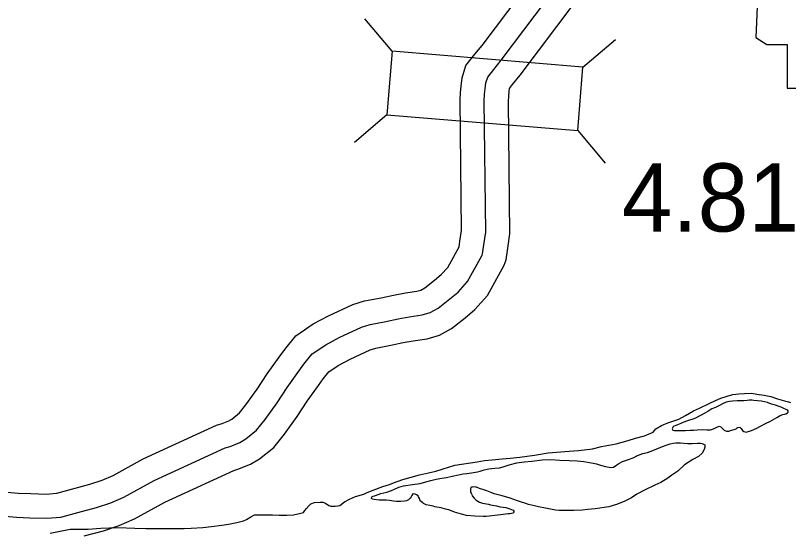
# Model space of a CAD drawing. Extents: x 31699 to 244310, y -8841 to 11474.
# Drawn here: x 98137.1 to 98456.9, y 2842.4 to 3055.8 of the extents above; entities that cross this region are included whole.
import ezdxf

# ---------------------------------------------------------------- set-up
doc = ezdxf.new("R2010")
doc.units = 0
for name, color, linetype in [('B_Logo', 7, 'Continuous'), ('G-ANNO-TEXT', 7, 'Continuous'), ('Level 55', 7, 'Continuous'), ('R_Draft', 7, 'Continuous'), ('R_XS_EARTHWORK_STAGE1', 7, 'Continuous'), ('S_WALL', 7, 'Continuous')]:
    doc.layers.add(name, color=color, linetype=linetype)

msp = doc.modelspace()

# ---------------------------------------------------------------- linework, layer by layer
at = {"layer": 'B_Logo'}
msp.add_lwpolyline([(98132.93, 2848.75), (98137.53, 2848.36), (98143.06, 2848.11), (98150.11, 2847.92), (98155.91, 2848.4), (98162.82, 2850.28), (98170.61, 2852.37), (98176.46, 2854.25), (98181.92, 2856.67), (98194.41, 2863.5), (98223.87, 2877.05), (98225.87, 2877.65), (98229.86, 2879.2), (98232.32, 2880.74), (98236.83, 2884.29), (98240.42, 2888.77), (98245.32, 2895.58), (98249.44, 2901.93), (98254.28, 2908.69), (98256.4, 2911.63), (98259.85, 2915.91), (98265.43, 2919.66), (98271.02, 2922.61), (98280.19, 2926.97), (98283.85, 2928.04), (98290.37, 2929.26), (98295.43, 2930.4), (98300.02, 2931.21), (98305.28, 2931.96), (98308.61, 2932.97), (98312, 2934.78), (98316.78, 2938.59), (98320.17, 2941.4), (98324.15, 2945.82), (98330.11, 2956.71), (98330.31, 2957.24), (98330.83, 2960.98), (98331.62, 2966.19), (98331, 3020.52), (98331.19, 3023.2), (98331.39, 3025.53), (98331.71, 3027.94), (98332.44, 3030.34), (98334.96, 3033.48), (98338.01, 3037.29), (98375.89, 3087.57)], dxfattribs=at)
at = {"layer": 'G-ANNO-TEXT'}
msp.add_lwpolyline([(98440.55, 3131.83), (98445.63, 3097.99), (98443.37, 3046.68), (98447.88, 3043.86), (98456.34, 3043.86), (98456.34, 3025.81), (98527.4, 3025.81), (98530.78, 3033.14), (98529.65, 3044.98), (98531.34, 3058.52), (98537.55, 3069.23), (98541.49, 3077.13), (98547.13, 3085.59), (98550.52, 3094.61), (98553.34, 3101.94), (98558.41, 3108.14), (98559.54, 3112.09), (98557.28, 3114.91), (98539.8, 3114.91), (98543.75, 3122.81), (98544.31, 3127.88), (98541.98, 3131.78)], close=True, dxfattribs=at)
at = {"layer": 'Level 55'}
for points in [[(98133.66, 2858.73), (98138.18, 2858.34), (98143.42, 2858.1), (98149.83, 2857.93), (98154.16, 2858.29), (98160.22, 2859.94), (98167.78, 2861.97), (98172.9, 2863.61), (98177.48, 2865.64), (98189.92, 2872.44), (98220.31, 2886.42), (98222.61, 2887.11), (98225.36, 2888.18), (98226.56, 2888.93), (98229.75, 2891.44), (98232.45, 2894.81), (98237.06, 2901.23), (98241.17, 2907.57), (98246.16, 2914.53), (98248.45, 2917.7), (98253.02, 2923.36), (98260.29, 2928.25), (98266.53, 2931.55), (98276.61, 2936.34), (98281.52, 2937.78), (98288.35, 2939.05), (98293.45, 2940.21), (98298.45, 2941.09), (98303.11, 2941.75), (98304.76, 2942.25), (98306.48, 2943.17), (98310.47, 2946.35), (98313.23, 2948.64), (98315.94, 2951.65), (98320.63, 2960.21), (98320.94, 2962.42), (98321.61, 2966.88), (98321, 3020.83), (98321.22, 3023.97), (98321.44, 3026.62), (98321.91, 3030.07), (98323.43, 3035.09), (98327.16, 3039.74), (98330.12, 3043.43), (98367.92, 3093.61)], [(98165.43, 2840.63), (98173.43, 2842.77), (98180.03, 2844.89), (98186.35, 2847.69), (98198.91, 2854.56), (98227.43, 2867.68), (98229.13, 2868.19), (98234.36, 2870.22), (98238.07, 2872.55), (98243.92, 2877.14), (98248.38, 2882.72), (98253.59, 2889.94), (98257.7, 2896.3), (98262.4, 2902.85), (98264.35, 2905.56), (98266.68, 2908.45), (98270.57, 2911.06), (98275.5, 2913.66), (98283.77, 2917.59), (98286.18, 2918.3), (98292.39, 2919.46), (98297.41, 2920.6), (98301.59, 2921.34), (98307.44, 2922.17), (98312.45, 2923.68), (98317.51, 2926.39), (98323.09, 2930.83), (98327.11, 2934.17), (98332.36, 2939.99), (98339.23, 2952.55), (98340.06, 2954.78), (98340.73, 2959.55), (98341.63, 2965.5), (98341.01, 3020.22), (98341.16, 3022.42), (98341.33, 3024.45), (98341.49, 3025.65), (98342.76, 3027.23), (98345.91, 3031.16), (98383.86, 3081.53)]]:
    msp.add_lwpolyline(points, dxfattribs=at)
at = {"layer": 'R_Draft'}
for points in [[(98379.47, 2877.58), (98385.59, 2878.66), (98390.51, 2880.01), (98393.64, 2881.02), (98397.36, 2882.03), (98400.95, 2883.5), (98401.95, 2884.84), (98404.34, 2886.31), (98407, 2887.39), (98409.86, 2888.39), (98411.59, 2888.93), (98414.32, 2890.34), (98417.57, 2892.28), (98420.03, 2893.49), (98424.02, 2895.43), (98426.68, 2896.64), (98428.88, 2897.51), (98431.47, 2898.45), (98433.87, 2899.12), (98436.33, 2899.33), (98438.66, 2899.47), (98441.59, 2899.61), (98443.79, 2899.21), (98446.85, 2898.82), (98449.52, 2898.22), (98452.38, 2897.23), (98455.18, 2896.43), (98456.85, 2896.04), (98457.78, 2895.84)], [(98379.47, 2877.58), (98385.59, 2878.66), (98390.51, 2880.01), (98393.64, 2881.02), (98397.36, 2882.03), (98400.95, 2883.5), (98401.95, 2884.84), (98404.34, 2886.31), (98407, 2887.39), (98409.86, 2888.39), (98411.59, 2888.93), (98414.32, 2890.34), (98417.57, 2892.28), (98420.03, 2893.49), (98424.02, 2895.43), (98426.68, 2896.64), (98428.88, 2897.51), (98431.47, 2898.45), (98433.87, 2899.12), (98436.33, 2899.33), (98438.66, 2899.47), (98441.59, 2899.61), (98443.79, 2899.21), (98446.85, 2898.82), (98449.52, 2898.22), (98452.38, 2897.23), (98455.18, 2896.43), (98456.85, 2896.04), (98457.78, 2895.84)], [(98452.07, 2889.55), (98453.47, 2890.36), (98454.6, 2890.76), (98455.2, 2890.96), (98455.73, 2891.16), (98456.53, 2891.5), (98456.72, 2891.83), (98456.72, 2892.03), (98456.59, 2892.43), (98456.26, 2892.76), (98454.99, 2893.36), (98453.86, 2893.83), (98452.59, 2894.29), (98451.46, 2894.62), (98449.92, 2895.15), (98448.26, 2895.75), (98446.99, 2896.02), (98445.59, 2896.28), (98442.53, 2896.67), (98441.73, 2896.74), (98440.73, 2896.74), (98439.8, 2896.6), (98438.4, 2896.53), (98437.4, 2896.46), (98435.61, 2896.53), (98433.74, 2896.39), (98432.54, 2896.25), (98431.15, 2895.85), (98429.55, 2895.18), (98428.29, 2894.51), (98426.69, 2893.77), (98425.16, 2893.1), (98423.57, 2892.09), (98421.97, 2891.29), (98420.71, 2890.49), (98419.64, 2889.95)], [(98452.07, 2889.55), (98453.47, 2890.36), (98454.6, 2890.76), (98455.2, 2890.96), (98455.73, 2891.16), (98456.53, 2891.5), (98456.72, 2891.83), (98456.72, 2892.03), (98456.59, 2892.43), (98456.26, 2892.76), (98454.99, 2893.36), (98453.86, 2893.83), (98452.59, 2894.29), (98451.46, 2894.62), (98449.92, 2895.15), (98448.26, 2895.75), (98446.99, 2896.02), (98445.59, 2896.28), (98442.53, 2896.67), (98441.73, 2896.74), (98440.73, 2896.74), (98439.8, 2896.6), (98438.4, 2896.53), (98437.4, 2896.46), (98435.61, 2896.53), (98433.74, 2896.39), (98432.54, 2896.25), (98431.15, 2895.85), (98429.55, 2895.18), (98428.29, 2894.51), (98426.69, 2893.77), (98425.16, 2893.1), (98423.57, 2892.09), (98421.97, 2891.29), (98420.71, 2890.49), (98419.64, 2889.95)], [(98419.64, 2889.95), (98418.45, 2889.35), (98416.92, 2888.81), (98416.32, 2888.61), (98414.72, 2888), (98413.59, 2887.67), (98412.86, 2887.33), (98412.33, 2887.13), (98411.6, 2886.8), (98410.93, 2886.53), (98410, 2886.12), (98409.47, 2885.99), (98409, 2885.52), (98408.87, 2885.19), (98408.81, 2884.85), (98409.07, 2884.39), (98409.74, 2884.25), (98411.74, 2884.26), (98414.27, 2884.2), (98416.26, 2884.34), (98417.53, 2884.4), (98419.13, 2884.48), (98421.39, 2884.55), (98423.06, 2884.48), (98423.99, 2884.42), (98424.65, 2884.42), (98425.92, 2884.96), (98426.65, 2885.29), (98427.31, 2885.63), (98427.71, 2885.76), (98428.18, 2885.96), (98428.91, 2885.76), (98429.71, 2884.9), (98430.25, 2884.37), (98431.18, 2883.9), (98432.24, 2883.97), (98433.31, 2884.37), (98434.44, 2884.64), (98435.24, 2884.91), (98435.7, 2885.31), (98435.97, 2885.51), (98436.77, 2885.65), (98437.37, 2884.98), (98437.9, 2884.25), (98438.44, 2883.78), (98439.37, 2883.45), (98441.57, 2884.19), (98443.76, 2885.2), (98445.02, 2885.87), (98447.62, 2887.21), (98449.21, 2887.88), (98452.07, 2889.55)], [(98419.64, 2889.95), (98418.45, 2889.35), (98416.92, 2888.81), (98416.32, 2888.61), (98414.72, 2888), (98413.59, 2887.67), (98412.86, 2887.33), (98412.33, 2887.13), (98411.6, 2886.8), (98410.93, 2886.53), (98410, 2886.12), (98409.47, 2885.99), (98409, 2885.52), (98408.87, 2885.19), (98408.81, 2884.85), (98409.07, 2884.39), (98409.74, 2884.25), (98411.74, 2884.26), (98414.27, 2884.2), (98416.26, 2884.34), (98417.53, 2884.4), (98419.13, 2884.48), (98421.39, 2884.55), (98423.06, 2884.48), (98423.99, 2884.42), (98424.65, 2884.42), (98425.92, 2884.96), (98426.65, 2885.29), (98427.31, 2885.63), (98427.71, 2885.76), (98428.18, 2885.96), (98428.91, 2885.76), (98429.71, 2884.9), (98430.25, 2884.37), (98431.18, 2883.9), (98432.24, 2883.97), (98433.31, 2884.37), (98434.44, 2884.64), (98435.24, 2884.91), (98435.7, 2885.31), (98435.97, 2885.51), (98436.77, 2885.65), (98437.37, 2884.98), (98437.9, 2884.25), (98438.44, 2883.78), (98439.37, 2883.45), (98441.57, 2884.19), (98443.76, 2885.2), (98445.02, 2885.87), (98447.62, 2887.21), (98449.21, 2887.88), (98452.07, 2889.55)], [(98400.71, 2875.96), (98402.44, 2876.56), (98404.77, 2877.57), (98406.23, 2878.17), (98407.96, 2878.64), (98409.16, 2878.91), (98410.22, 2879.05), (98412.15, 2879.05), (98413.62, 2878.99), (98415.28, 2878.86), (98417.01, 2878.86), (98419.21, 2878.93), (98420.47, 2879), (98421.14, 2878.87), (98421.74, 2878.61), (98422.27, 2878.21), (98422.34, 2877.87), (98422.28, 2877.27), (98421.95, 2876.34), (98421.22, 2874.87), (98419.69, 2873.46), (98417.3, 2872.26), (98413.84, 2870.05), (98411.12, 2867.44), (98408.66, 2865.76), (98406.93, 2864.49), (98404.14, 2862.75), (98401.61, 2861.61), (98397.56, 2859.73), (98394.1, 2857.85), (98391.91, 2856.38), (98388.92, 2854.91), (98385.79, 2853.63), (98382.6, 2852.69), (98376.94, 2851.81), (98373.88, 2851.54), (98371.48, 2851.26), (98368.09, 2851.12), (98363.49, 2851.18), (98362.03, 2851.11), (98360.5, 2851.31), (98356.3, 2852.03), (98353.5, 2852.63), (98351.84, 2853.02), (98349.3, 2853.62), (98348.17, 2854.02), (98346.5, 2854.62), (98344.77, 2855.15), (98341.77, 2856.27), (98338.38, 2857.13), (98336.78, 2857.6), (98335.18, 2858.06), (98334.18, 2858.39), (98332.11, 2859.19), (98330.78, 2859.72), (98329.11, 2860.19), (98327.78, 2860.72), (98327.45, 2860.78), (98326.45, 2860.85), (98326.05, 2860.78), (98325.78, 2860.71), (98325.45, 2860.58), (98325.32, 2859.98), (98325.32, 2859.64), (98325.32, 2859.04), (98325.39, 2858.71), (98325.59, 2858.31), (98325.86, 2857.78), (98326.06, 2857.24), (98326.79, 2856.24), (98327.66, 2855.44), (98329.06, 2854.64), (98330.26, 2854.18), (98332.79, 2853.72), (98333.66, 2853.45), (98336.06, 2852.99), (98337.66, 2852.66), (98338.79, 2852.53), (98339.92, 2852.33), (98340.72, 2852.07), (98341.59, 2851.87), (98342.32, 2851.54), (98342.92, 2851.2), (98343.32, 2850.87), (98343.32, 2850.47), (98343.12, 2850.14), (98342.79, 2850), (98341.72, 2849.8), (98340.86, 2849.73), (98339.86, 2849.66), (98338.86, 2849.53), (98335.4, 2849.12), (98331.87, 2848.71), (98330.54, 2848.64), (98327.08, 2848.83)], [(98400.71, 2875.96), (98402.44, 2876.56), (98404.77, 2877.57), (98406.23, 2878.17), (98407.96, 2878.64), (98409.16, 2878.91), (98410.22, 2879.05), (98412.15, 2879.05), (98413.62, 2878.99), (98415.28, 2878.86), (98417.01, 2878.86), (98419.21, 2878.93), (98420.47, 2879), (98421.14, 2878.87), (98421.74, 2878.61), (98422.27, 2878.21), (98422.34, 2877.87), (98422.28, 2877.27), (98421.95, 2876.34), (98421.22, 2874.87), (98419.69, 2873.46), (98417.3, 2872.26), (98413.84, 2870.05), (98411.12, 2867.44), (98408.66, 2865.76), (98406.93, 2864.49), (98404.14, 2862.75), (98401.61, 2861.61), (98397.56, 2859.73), (98394.1, 2857.85), (98391.91, 2856.38), (98388.92, 2854.91), (98385.79, 2853.63), (98382.6, 2852.69), (98376.94, 2851.81), (98373.88, 2851.54), (98371.48, 2851.26), (98368.09, 2851.12), (98363.49, 2851.18), (98362.03, 2851.11), (98360.5, 2851.31), (98356.3, 2852.03), (98353.5, 2852.63), (98351.84, 2853.02), (98349.3, 2853.62), (98348.17, 2854.02), (98346.5, 2854.62), (98344.77, 2855.15), (98341.77, 2856.27), (98338.38, 2857.13), (98336.78, 2857.6), (98335.18, 2858.06), (98334.18, 2858.39), (98332.11, 2859.19), (98330.78, 2859.72), (98329.11, 2860.19), (98327.78, 2860.72), (98327.45, 2860.78), (98326.45, 2860.85), (98326.05, 2860.78), (98325.78, 2860.71), (98325.45, 2860.58), (98325.32, 2859.98), (98325.32, 2859.64), (98325.32, 2859.04), (98325.39, 2858.71), (98325.59, 2858.31), (98325.86, 2857.78), (98326.06, 2857.24), (98326.79, 2856.24), (98327.66, 2855.44), (98329.06, 2854.64), (98330.26, 2854.18), (98332.79, 2853.72), (98333.66, 2853.45), (98336.06, 2852.99), (98337.66, 2852.66), (98338.79, 2852.53), (98339.92, 2852.33), (98340.72, 2852.07), (98341.59, 2851.87), (98342.32, 2851.54), (98342.92, 2851.2), (98343.32, 2850.87), (98343.32, 2850.47), (98343.12, 2850.14), (98342.79, 2850), (98341.72, 2849.8), (98340.86, 2849.73), (98339.86, 2849.66), (98338.86, 2849.53), (98335.4, 2849.12), (98331.87, 2848.71), (98330.54, 2848.64), (98327.08, 2848.83)], [(98151.4, 2841.78), (98159.65, 2843.34), (98167.17, 2843.42), (98172.36, 2843.76), (98179.42, 2844.05), (98186.41, 2843.79), (98191.07, 2843.67), (98197, 2843.68), (98201.33, 2843.62), (98206.85, 2843.7), (98209.71, 2843.78), (98214.64, 2844.12), (98218.23, 2844.53), (98222.43, 2845), (98225.22, 2845.48), (98228.62, 2846.15), (98231.48, 2846.89), (98232.61, 2847.36), (98234.4, 2848.57), (98235.93, 2849.37), (98241.32, 2849.38), (98243.45, 2849.39), (98246.18, 2849.26), (98249.38, 2849.13), (98252.04, 2849.27), (98255.17, 2850.01), (98256.23, 2850.35), (98256.77, 2851.15), (98257.43, 2852.02), (98258.56, 2853.16), (98259.29, 2853.83), (98260.82, 2854.5), (98263.15, 2854.64), (98264.28, 2854.57), (98265.28, 2854.11), (98266.68, 2853.24), (98267.61, 2852.91), (98268.28, 2852.85), (98269.28, 2852.85), (98271.27, 2853.25), (98273.2, 2854.66), (98275.33, 2855.8), (98277.79, 2856.87), (98281.25, 2857.88), (98282.58, 2858.62), (98285.11, 2859.49), (98289.1, 2861.1), (98291.82, 2861.91), (98293.49, 2862.58), (98297.28, 2863.99), (98300.8, 2864.86), (98304.26, 2865.81), (98307.92, 2866.75), (98311.05, 2867.42), (98318.83, 2869.84), (98328.08, 2871.26), (98331.14, 2871.74), (98334.27, 2872.14), (98338.47, 2872.42), (98341.79, 2872.76), (98345.72, 2873.17), (98351.78, 2874.05), (98357.5, 2874.93), (98366.15, 2875.68), (98370.02, 2875.96), (98375.81, 2876.57), (98379.47, 2877.58)], [(98178.02, 2843.99), (98179.42, 2844.05), (98186.41, 2843.79), (98191.07, 2843.67), (98197, 2843.68), (98201.33, 2843.62), (98206.85, 2843.7), (98209.71, 2843.78), (98214.64, 2844.12), (98218.23, 2844.53), (98222.43, 2845), (98225.22, 2845.48), (98228.62, 2846.15), (98231.48, 2846.89), (98232.61, 2847.36), (98234.4, 2848.57), (98235.93, 2849.37), (98241.32, 2849.38), (98243.45, 2849.39), (98246.18, 2849.26), (98249.38, 2849.13), (98252.04, 2849.27), (98255.17, 2850.01), (98256.23, 2850.35), (98256.77, 2851.15), (98257.43, 2852.02), (98258.56, 2853.16), (98259.29, 2853.83), (98260.82, 2854.5), (98263.15, 2854.64), (98264.28, 2854.57), (98265.28, 2854.11), (98266.68, 2853.24), (98267.61, 2852.91), (98268.28, 2852.85), (98269.28, 2852.85), (98271.27, 2853.25), (98273.2, 2854.66), (98275.33, 2855.8), (98277.79, 2856.87), (98281.25, 2857.88), (98282.58, 2858.62), (98285.11, 2859.49), (98289.1, 2861.1), (98291.82, 2861.91), (98293.49, 2862.58), (98297.28, 2863.99), (98300.8, 2864.86), (98304.26, 2865.81), (98307.92, 2866.75), (98311.05, 2867.42), (98318.83, 2869.84), (98328.08, 2871.26), (98331.14, 2871.74), (98334.27, 2872.14), (98338.47, 2872.42), (98341.79, 2872.76), (98345.72, 2873.17), (98351.78, 2874.05), (98357.5, 2874.93), (98366.15, 2875.68), (98370.02, 2875.96), (98375.81, 2876.57), (98379.47, 2877.58)], [(98327.08, 2848.83), (98323.68, 2849.03), (98321.62, 2849.56), (98318.75, 2850.48), (98316.35, 2851.41), (98315.02, 2851.74), (98313.22, 2852.21), (98310.62, 2852.67), (98309.89, 2852.87), (98308.49, 2853.13), (98307.03, 2853.46), (98305.83, 2854.06), (98305.56, 2854.26), (98304.56, 2855.19), (98304.22, 2856.06), (98303.76, 2856.73), (98303.62, 2857.13), (98303.02, 2857.66), (98302.42, 2857.86), (98301.42, 2857.99), (98301.02, 2857.32), (98300.83, 2856.72), (98300.36, 2856.25), (98299.63, 2855.52), (98298.9, 2855.18), (98297.97, 2854.98), (98296.5, 2854.78), (98294.71, 2854.91), (98293.51, 2855.04), (98291.77, 2855.3), (98290.38, 2855.36), (98289.38, 2855.43), (98287.58, 2855.36), (98286.45, 2855.49), (98285.45, 2855.69), (98284.98, 2855.82), (98284.58, 2855.95), (98284.38, 2856.15), (98284.31, 2856.35), (98284.65, 2856.95), (98286.04, 2857.36), (98288.17, 2858.1), (98290.7, 2858.77), (98292.7, 2859.37), (98293.83, 2859.98), (98295.75, 2860.71), (98297.68, 2861.32), (98298.55, 2861.46), (98300.35, 2861.73), (98302.34, 2862), (98304.47, 2862.34), (98306.87, 2863.01), (98308.93, 2863.55), (98311.19, 2864.09), (98313.52, 2864.49), (98315.38, 2864.83), (98317.78, 2865.3), (98320.37, 2865.84), (98322.24, 2866.24), (98323.77, 2866.45), (98325.77, 2866.72), (98328.16, 2867.06), (98329.29, 2867.33), (98331.02, 2867.93), (98332.95, 2868.4), (98335.41, 2868.61), (98337.34, 2868.81), (98338.87, 2869.22), (98341.27, 2870.02), (98344.53, 2870.83), (98347.59, 2871.31), (98350.65, 2871.58), (98355.05, 2872.06), (98358.57, 2872.2), (98362.24, 2871.87), (98366.17, 2871.75), (98369.43, 2871.69), (98372.16, 2871.42), (98375.42, 2870.83), (98377.49, 2870.44), (98379.09, 2869.9), (98381.15, 2869.31), (98383.42, 2868.85), (98384.48, 2869.05), (98385.88, 2870.05), (98386.67, 2870.59), (98388.2, 2871.33), (98390.27, 2872.13), (98392.66, 2872.94), (98394.39, 2873.88), (98396.58, 2874.75), (98398.58, 2875.15), (98400.71, 2875.96)], [(98327.08, 2848.83), (98323.68, 2849.03), (98321.62, 2849.56), (98318.75, 2850.48), (98316.35, 2851.41), (98315.02, 2851.74), (98313.22, 2852.21), (98310.62, 2852.67), (98309.89, 2852.87), (98308.49, 2853.13), (98307.03, 2853.46), (98305.83, 2854.06), (98305.56, 2854.26), (98304.56, 2855.19), (98304.22, 2856.06), (98303.76, 2856.73), (98303.62, 2857.13), (98303.02, 2857.66), (98302.42, 2857.86), (98301.42, 2857.99), (98301.02, 2857.32), (98300.83, 2856.72), (98300.36, 2856.25), (98299.63, 2855.52), (98298.9, 2855.18), (98297.97, 2854.98), (98296.5, 2854.78), (98294.71, 2854.91), (98293.51, 2855.04), (98291.77, 2855.3), (98290.38, 2855.36), (98289.38, 2855.43), (98287.58, 2855.36), (98286.45, 2855.49), (98285.45, 2855.69), (98284.98, 2855.82), (98284.58, 2855.95), (98284.38, 2856.15), (98284.31, 2856.35), (98284.65, 2856.95), (98286.04, 2857.36), (98288.17, 2858.1), (98290.7, 2858.77), (98292.7, 2859.37), (98293.83, 2859.98), (98295.75, 2860.71), (98297.68, 2861.32), (98298.55, 2861.46), (98300.35, 2861.73), (98302.34, 2862), (98304.47, 2862.34), (98306.87, 2863.01), (98308.93, 2863.55), (98311.19, 2864.09), (98313.52, 2864.49), (98315.38, 2864.83), (98317.78, 2865.3), (98320.37, 2865.84), (98322.24, 2866.24), (98323.77, 2866.45), (98325.77, 2866.72), (98328.16, 2867.06), (98329.29, 2867.33), (98331.02, 2867.93), (98332.95, 2868.4), (98335.41, 2868.61), (98337.34, 2868.81), (98338.87, 2869.22), (98341.27, 2870.02), (98344.53, 2870.83), (98347.59, 2871.31), (98350.65, 2871.58), (98355.05, 2872.06), (98358.57, 2872.2), (98362.24, 2871.87), (98366.17, 2871.75), (98369.43, 2871.69), (98372.16, 2871.42), (98375.42, 2870.83), (98377.49, 2870.44), (98379.09, 2869.9), (98381.15, 2869.31), (98383.42, 2868.85), (98384.48, 2869.05), (98385.88, 2870.05), (98386.67, 2870.59), (98388.2, 2871.33), (98390.27, 2872.13), (98392.66, 2872.94), (98394.39, 2873.88), (98396.58, 2874.75), (98398.58, 2875.15), (98400.71, 2875.96)]]:
    msp.add_lwpolyline(points, dxfattribs=at)
at = {"layer": 'R_XS_EARTHWORK_STAGE1'}
for p, q in [((98292.93, 3041.02), (98281.56, 3054.45)), ((98371.86, 3034.49), (98385.29, 3045.87)), ((98290.76, 3014.71), (98277.33, 3003.34)), ((98369.69, 3008.18), (98381.06, 2994.76))]:
    msp.add_line(p, q, dxfattribs=at)
msp.add_lwpolyline([(98290.76, 3014.71), (98369.69, 3008.18), (98371.86, 3034.49), (98292.93, 3041.02)], close=True, dxfattribs=at)

# ---------------------------------------------------------------- texts
at = {"layer": 'S_WALL'}
msp.add_text('4.81', height=28.16, dxfattribs=at).set_placement((98387.94, 2966.48))

doc.saveas('drawing.dxf')
